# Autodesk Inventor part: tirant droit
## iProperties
Shininess: 64.0
Length Units: 11269
Angle Units: 11279
Time Units: 11290
Mass Units: 11283
Length Display Precision: 3
Angle Display Precision: 2
Compacted: True
Part Number: tirant droit
Document SubType Name: Modeling
Created: 2004-12
Material: Par défaut
Designer: LEGERET Philippe
Density: 0.0
Volumn: 0.0
Area: 0.0
PropertySet Name: Model Information
Control State: 0
Master: False
Checked Out: False
Author: LEGERET Philippe
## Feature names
1. Extrusion1
2. Chanfrein1 [Chamfer]
3. Perçage1 [Hole]
4. Extrusion2
5. Chanfrein2 [Chamfer]
